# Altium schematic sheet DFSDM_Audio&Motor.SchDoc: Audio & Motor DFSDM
size A4; Date: Not used; ApprovedBy: Not used; CheckedBy: Not used; Author: Not used; CompanyName: STMicroelectronics; DrawnBy: Not used; Engineer: Not used; Organization: Not used; Address1: Not used; Address2: Not used; Address3: Not used; Address4: Not used; DocumentNumber: Not used; Revision: Not used; SheetNumber: 11; SheetTotal: 23
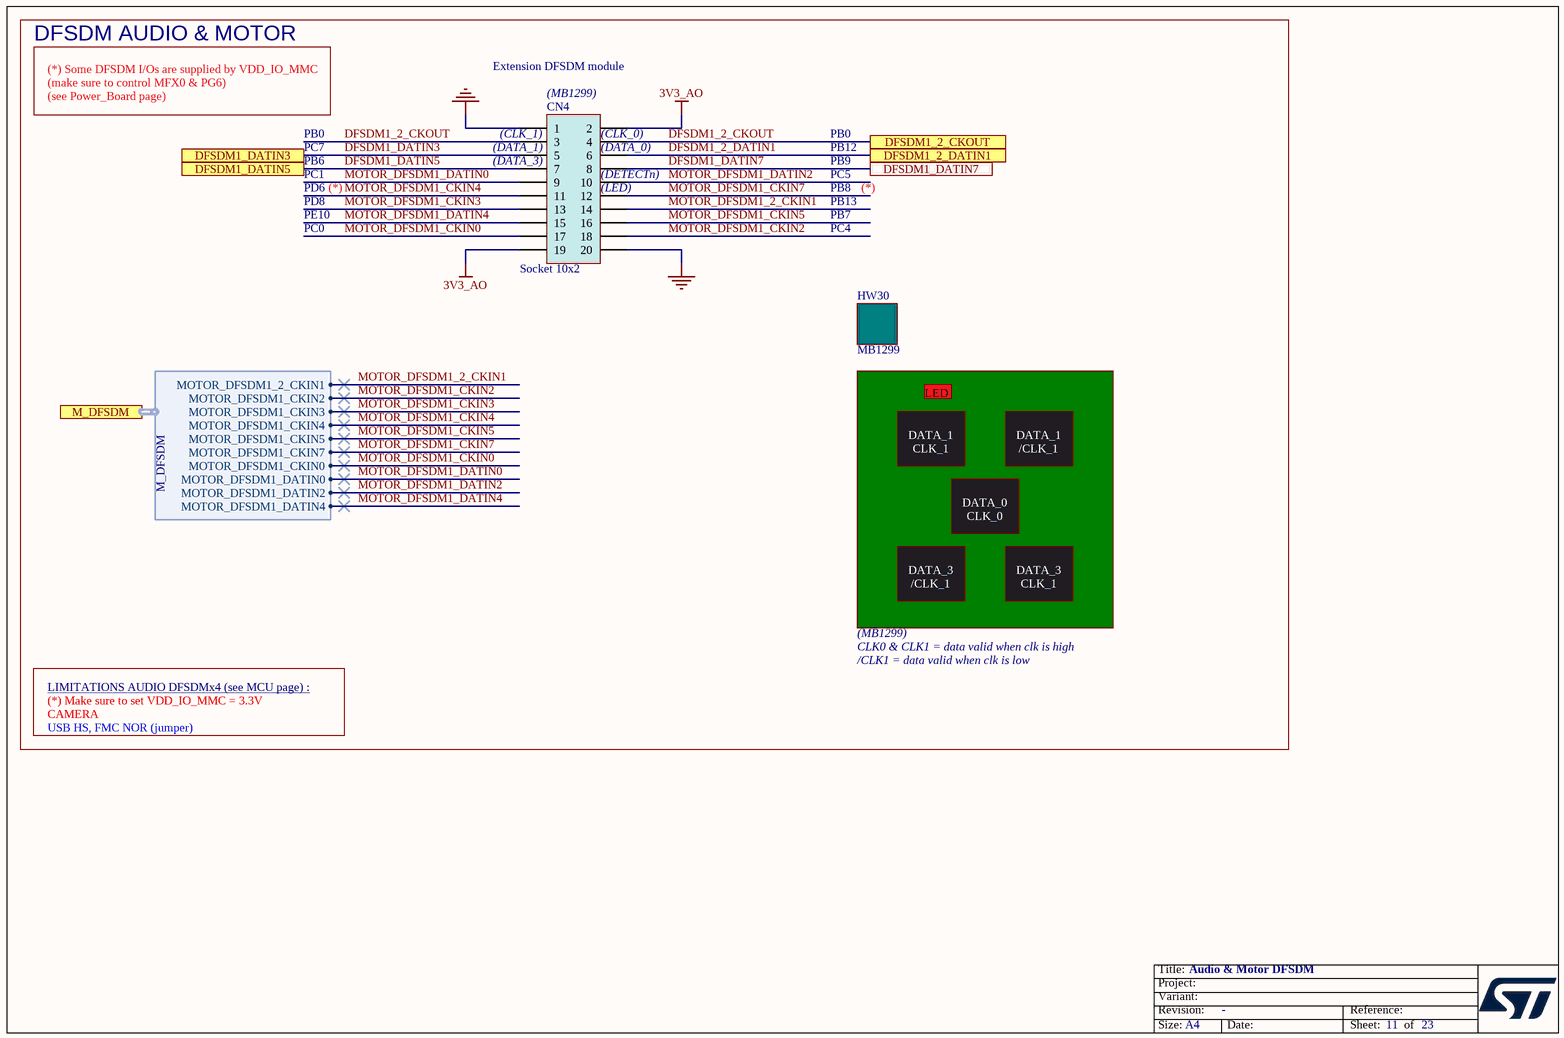
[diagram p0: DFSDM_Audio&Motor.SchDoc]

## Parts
CN4  Socket 10x2  [CON_FCI_20021311-XXX20XXLF]
HW30  value MB1299  [MOD_MB1299_5-MEMS_MICROPHONE-EXPANSION-BOARD]  (hidden comment: Daughter_Board)

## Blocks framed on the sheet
DFSDM AUDIO & MOTOR: CN4 HW30

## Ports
DFSDM1_2_CKOUT, DFSDM1_2_DATIN1, DFSDM1_DATIN3, DFSDM1_DATIN5, DFSDM1_DATIN7, M_DFSDM (harness M_DFSDM)

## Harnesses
M_DFSDM: MOTOR_DFSDM1_2_CKIN1, MOTOR_DFSDM1_CKIN3, MOTOR_DFSDM1_CKIN5, MOTOR_DFSDM1_CKIN7, MOTOR_DFSDM1_CKIN2, MOTOR_DFSDM1_CKIN4, MOTOR_DFSDM1_CKIN0, MOTOR_DFSDM1_DATIN0, MOTOR_DFSDM1_DATIN2, MOTOR_DFSDM1_DATIN4

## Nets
3V3_AO: CN4.2 CN4.19
GND: CN4.1 CN4.20
DFSDM1_2_CKOUT: CN4.3 CN4.4 ; port DFSDM1_2_CKOUT
DFSDM1_2_DATIN1: CN4.6 ; port DFSDM1_2_DATIN1
DFSDM1_DATIN3: CN4.5 ; port DFSDM1_DATIN3
DFSDM1_DATIN5: CN4.7 ; port DFSDM1_DATIN5
DFSDM1_DATIN7: CN4.8 ; port DFSDM1_DATIN7
MOTOR_DFSDM1_2_CKIN1: CN4.14 ; port M_DFSDM.MOTOR_DFSDM1_2_CKIN1
MOTOR_DFSDM1_CKIN0: CN4.17 ; port M_DFSDM.MOTOR_DFSDM1_CKIN0
MOTOR_DFSDM1_CKIN2: CN4.18 ; port M_DFSDM.MOTOR_DFSDM1_CKIN2
MOTOR_DFSDM1_CKIN3: CN4.13 ; port M_DFSDM.MOTOR_DFSDM1_CKIN3
MOTOR_DFSDM1_CKIN4: CN4.11 ; port M_DFSDM.MOTOR_DFSDM1_CKIN4
MOTOR_DFSDM1_CKIN5: CN4.16 ; port M_DFSDM.MOTOR_DFSDM1_CKIN5
MOTOR_DFSDM1_CKIN7: CN4.12 ; port M_DFSDM.MOTOR_DFSDM1_CKIN7
MOTOR_DFSDM1_DATIN0: CN4.9 ; port M_DFSDM.MOTOR_DFSDM1_DATIN0
MOTOR_DFSDM1_DATIN2: CN4.10 ; port M_DFSDM.MOTOR_DFSDM1_DATIN2
MOTOR_DFSDM1_DATIN4: CN4.15 ; port M_DFSDM.MOTOR_DFSDM1_DATIN4

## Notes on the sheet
- (*) Some DFSDM I/Os are supplied by VDD_IO_MMC
  (make sure to control MFX0 & PG6)
  (see Power_Board page)
- Extension DFSDM module
- (near CN4) (MB1299)
- PB0
- PB6
- PC7
- PC1
- (near CN4) (DATA_1)
- (near CN4) (DATA_3)
- (near CN4) (CLK_1)
- (near CN4) (CLK_0)
- (near CN4) (DATA_0)
- (near CN4) (DETECTn)
- PB12
- PB9
- PC5
- PD8
- PC0
- PD6
- PE10
- (*)
- (near CN4) (LED)
- PB13
- PB8
- PB7
- PC4
- DATA_1
  CLK_1
- LED
- DATA_1
  /CLK_1
- DATA_0
  CLK_0
- DATA_3
  /CLK_1
- DATA_3
  CLK_1
- (MB1299)
- CLK0 & CLK1 = data valid when clk is high
- LIMITATIONS AUDIO DFSDMx4 (see MCU page) :
- CAMERA
- (*) Make sure to set VDD_IO_MMC = 3.3V
- /CLK1 = data valid when clk is low
- USB HS, FMC NOR (jumper)

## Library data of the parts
CN4 = MCD-00147: Socket for MB1299, 10x2, 1.27mm, VR, TH, Height 4.30mm/2.40mm; Manufacturer_Part_Number: 20021311-00020T4LF; Manufacturer: AMPHENOL ICC; Part_Type: Connector; Alternate_Manufacturer_Part_Number: 234220S1410; Alternate_Manufacturer: JIUBABA; Part_Preference: Recommended; Partial_Alternate_Internal_Part_Number: MCD-03007; Provided_By: SUBCO; ECCN_US: EAR99; ECCN_EU: NEC; Component_Country_Of_Origin: China; ID: 2719; Order_Code_RS: 170-8859; ShowFields: YES
HW30 = MCD-01031: MB1299 : Expansion Board with 5 x MEMS Microphones; Part_Type: Misc; Manufacturer_Part_Number: MB1299 - 5 x MEMS Microphones Expansion Board; Manufacturer: STMICROELECTRONICS; Manufacturer_HQ_COO: EU; Part_Preference: Recommended; Provided_By: SUBCO with ST control; Component_Country_Of_Origin: Unknown; ID: 2993; ShowFields: YES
